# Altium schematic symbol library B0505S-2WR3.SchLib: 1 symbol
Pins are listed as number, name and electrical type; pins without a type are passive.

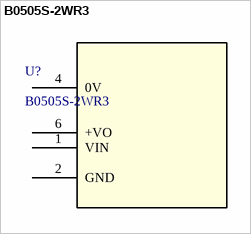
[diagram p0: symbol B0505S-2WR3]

## B0505S-2WR3
designator U?
Description; Manufacturer_Name: MORNSUN
footprint B_S-2WR2_MNS
pins: 1 VIN (power), 2 GND (power), 4 0V, 6 +VO (power)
